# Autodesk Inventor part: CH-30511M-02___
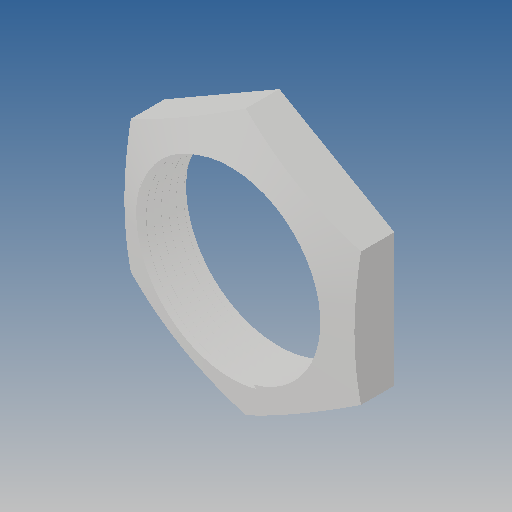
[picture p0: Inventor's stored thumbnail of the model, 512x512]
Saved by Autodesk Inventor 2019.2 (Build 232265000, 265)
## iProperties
Created: 2010-06
Part Number: CH-30511M-02___
Material: Ogólny
Document SubType Name: Modeling
Designer: CADENGINEERING4
Density: 1 g/cm^3
Appearance: Domyślna
Author: CADENGINEERING4
Revision Number: ANY
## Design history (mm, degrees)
feature "NONE"
node "Bryła1"
